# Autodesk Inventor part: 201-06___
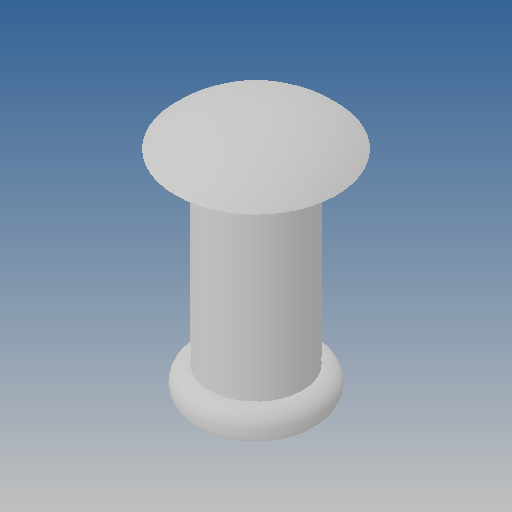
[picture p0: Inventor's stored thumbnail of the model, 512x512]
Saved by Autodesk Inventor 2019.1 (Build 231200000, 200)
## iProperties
Created: 2010-06
Part Number: 201-06___
Material: Ogólny
Document SubType Name: Modeling
Designer: CADENGINEERING4
Density: 1 g/cm^3
Appearance: Domyślna
Author: CADENGINEERING4
Revision Number: ANY
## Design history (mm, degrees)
feature "NONE"
node "Bryła1"
